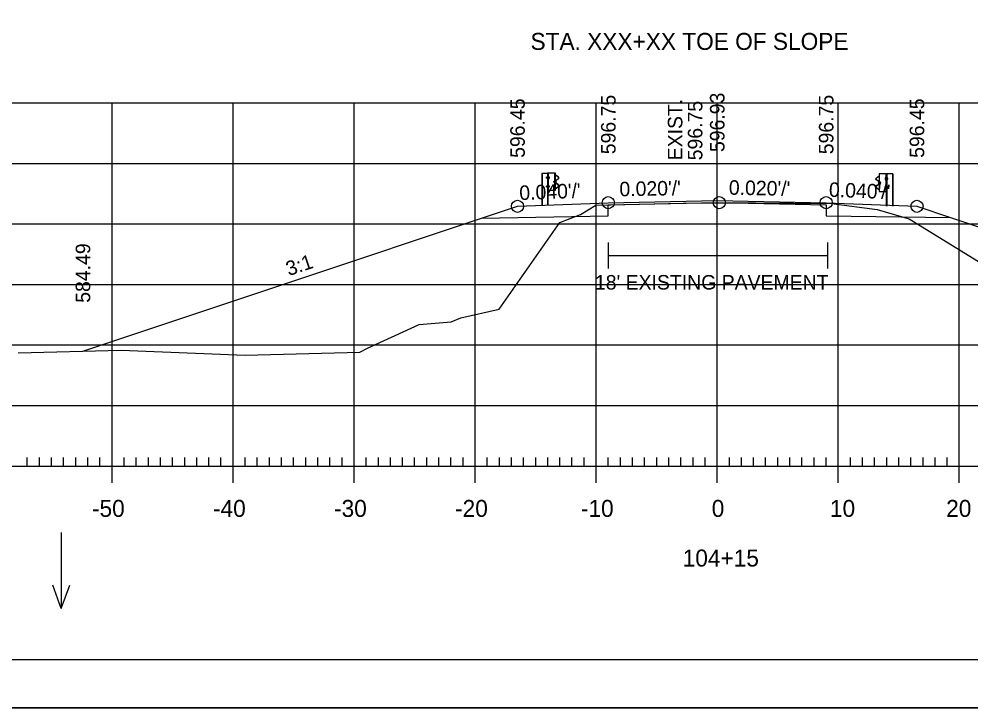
# Model space of a CAD drawing. Extents: x 961436 to 1372525, y 380079 to 2027791.
# Drawn here: x 1370576.1 to 1370654.8, y 380322.4 to 380379.3 of the extents above; entities that cross this region are included whole.
import ezdxf

# ---------------------------------------------------------------- set-up
doc = ezdxf.new("R2010")
doc.units = 0
for name, color, linetype in [('R_Alt Surface', 7, 'Continuous'), ('R_Axis', 7, 'Continuous'), ('R_Axis Annot', 7, 'Continuous'), ('R_Drive', 7, 'Continuous'), ('R_Exist Surface', 7, 'Continuous'), ('R_Fin Surface', 7, 'Continuous'), ('R_Fin Surface Annot', 7, 'Continuous'), ('R_Grid', 7, 'Continuous'), ('R_No Plot', 7, 'Continuous'), ('R_Proposed Road', 7, 'Continuous'), ('R_Water Annot', 7, 'Continuous'), ('R_Xsect Elev', 7, 'Continuous')]:
    doc.layers.add(name, color=color, linetype=linetype)

msp = doc.modelspace()

# ---------------------------------------------------------------- linework, layer by layer
at = {"layer": 'R_Alt Surface'}
msp.add_lwpolyline([(1370614.334, 380362.858), (1370624.812, 380363.068), (1370624.802, 380363.068), (1370624.812, 380363.985), (1370633.812, 380364.165), (1370642.812, 380363.985), (1370642.822, 380363.068), (1370642.812, 380363.068), (1370653.073, 380362.931)], dxfattribs=at)
at = {"layer": 'R_Axis'}
for p, q in [((1370583.812, 380340.997), (1370583.812, 380343.797)), ((1370593.812, 380340.997), (1370593.812, 380343.797)), ((1370603.812, 380340.997), (1370603.812, 380343.797)), ((1370613.812, 380340.997), (1370613.812, 380343.797)), ((1370623.812, 380340.997), (1370623.812, 380343.797)), ((1370633.812, 380340.997), (1370633.812, 380343.797)), ((1370643.812, 380340.997), (1370643.812, 380343.797)), ((1370653.812, 380340.997), (1370653.812, 380343.797)), ((1370576.812, 380342.397), (1370576.812, 380343.097)), ((1370577.812, 380342.397), (1370577.812, 380343.097)), ((1370578.812, 380342.397), (1370578.812, 380343.097)), ((1370579.812, 380342.397), (1370579.812, 380343.097)), ((1370580.812, 380342.397), (1370580.812, 380343.097)), ((1370581.812, 380342.397), (1370581.812, 380343.097)), ((1370582.812, 380342.397), (1370582.812, 380343.097)), ((1370584.812, 380342.397), (1370584.812, 380343.097)), ((1370585.812, 380342.397), (1370585.812, 380343.097)), ((1370586.812, 380342.397), (1370586.812, 380343.097)), ((1370587.812, 380342.397), (1370587.812, 380343.097)), ((1370588.812, 380342.397), (1370588.812, 380343.097)), ((1370589.812, 380342.397), (1370589.812, 380343.097)), ((1370590.812, 380342.397), (1370590.812, 380343.097)), ((1370591.812, 380342.397), (1370591.812, 380343.097)), ((1370592.812, 380342.397), (1370592.812, 380343.097)), ((1370594.812, 380342.397), (1370594.812, 380343.097)), ((1370595.812, 380342.397), (1370595.812, 380343.097)), ((1370596.812, 380342.397), (1370596.812, 380343.097)), ((1370597.812, 380342.397), (1370597.812, 380343.097)), ((1370598.812, 380342.397), (1370598.812, 380343.097)), ((1370599.812, 380342.397), (1370599.812, 380343.097)), ((1370600.812, 380342.397), (1370600.812, 380343.097)), ((1370601.812, 380342.397), (1370601.812, 380343.097)), ((1370602.812, 380342.397), (1370602.812, 380343.097)), ((1370604.812, 380342.397), (1370604.812, 380343.097)), ((1370605.812, 380342.397), (1370605.812, 380343.097)), ((1370606.812, 380342.397), (1370606.812, 380343.097)), ((1370607.812, 380342.397), (1370607.812, 380343.097)), ((1370608.812, 380342.397), (1370608.812, 380343.097)), ((1370609.812, 380342.397), (1370609.812, 380343.097)), ((1370610.812, 380342.397), (1370610.812, 380343.097)), ((1370611.812, 380342.397), (1370611.812, 380343.097)), ((1370612.812, 380342.397), (1370612.812, 380343.097)), ((1370614.812, 380342.397), (1370614.812, 380343.097)), ((1370615.812, 380342.397), (1370615.812, 380343.097)), ((1370616.812, 380342.397), (1370616.812, 380343.097)), ((1370617.812, 380342.397), (1370617.812, 380343.097)), ((1370618.812, 380342.397), (1370618.812, 380343.097)), ((1370619.812, 380342.397), (1370619.812, 380343.097)), ((1370620.812, 380342.397), (1370620.812, 380343.097)), ((1370621.812, 380342.397), (1370621.812, 380343.097)), ((1370622.812, 380342.397), (1370622.812, 380343.097)), ((1370624.812, 380342.397), (1370624.812, 380343.097)), ((1370625.812, 380342.397), (1370625.812, 380343.097)), ((1370626.812, 380342.397), (1370626.812, 380343.097)), ((1370627.812, 380342.397), (1370627.812, 380343.097)), ((1370628.812, 380342.397), (1370628.812, 380343.097)), ((1370629.812, 380342.397), (1370629.812, 380343.097)), ((1370630.812, 380342.397), (1370630.812, 380343.097)), ((1370631.812, 380342.397), (1370631.812, 380343.097)), ((1370632.812, 380342.397), (1370632.812, 380343.097)), ((1370634.812, 380342.397), (1370634.812, 380343.097)), ((1370635.812, 380342.397), (1370635.812, 380343.097)), ((1370636.812, 380342.397), (1370636.812, 380343.097)), ((1370637.812, 380342.397), (1370637.812, 380343.097)), ((1370638.812, 380342.397), (1370638.812, 380343.097)), ((1370639.812, 380342.397), (1370639.812, 380343.097)), ((1370640.812, 380342.397), (1370640.812, 380343.097)), ((1370641.812, 380342.397), (1370641.812, 380343.097)), ((1370642.812, 380342.397), (1370642.812, 380343.097)), ((1370644.812, 380342.397), (1370644.812, 380343.097)), ((1370645.812, 380342.397), (1370645.812, 380343.097)), ((1370646.812, 380342.397), (1370646.812, 380343.097)), ((1370647.812, 380342.397), (1370647.812, 380343.097)), ((1370648.812, 380342.397), (1370648.812, 380343.097)), ((1370649.812, 380342.397), (1370649.812, 380343.097)), ((1370650.812, 380342.397), (1370650.812, 380343.097)), ((1370651.812, 380342.397), (1370651.812, 380343.097)), ((1370652.812, 380342.397), (1370652.812, 380343.097)), ((1370493.812, 380342.397), (1370773.812, 380342.397))]:
    msp.add_line(p, q, dxfattribs=at)
at = {"layer": 'R_Drive'}
for p, q in [((1370624.798, 380360.859), (1370624.798, 380358.723)), ((1370642.926, 380360.859), (1370642.926, 380358.723)), ((1370624.798, 380359.791), (1370642.926, 380359.791))]:
    msp.add_line(p, q, dxfattribs=at)
at = {"layer": 'R_Exist Surface'}
msp.add_lwpolyline([(1370576.066, 380351.749), (1370584.562, 380351.962), (1370594.822, 380351.568), (1370604.291, 380351.812), (1370604.905, 380352.119), (1370609.172, 380354.091), (1370611.827, 380354.298), (1370612.619, 380354.639), (1370615.788, 380355.355), (1370620.797, 380362.515), (1370622.525, 380363.179), (1370623.787, 380363.938), (1370630.996, 380364.114), (1370633.983, 380364.15), (1370637.011, 380364.124), (1370643.25, 380364.093), (1370647.038, 380363.583), (1370649.681, 380362.807), (1370657.05, 380358.284)], dxfattribs=at)
at = {"layer": 'R_Fin Surface'}
msp.add_lwpolyline([(1370581.408, 380351.883), (1370599.495, 380357.91), (1370614.334, 380362.858), (1370617.312, 380363.851), (1370624.812, 380364.151), (1370633.812, 380364.331), (1370642.812, 380364.151), (1370650.312, 380363.851), (1370653.073, 380362.931), (1370664.147, 380359.237), (1370667.766, 380358.029), (1370680.532, 380353.778)], dxfattribs=at)
at = {"layer": 'R_Grid'}
for p, q in [((1370493.812, 380372.397), (1370773.812, 380372.397)), ((1370583.812, 380342.397), (1370583.812, 380372.397)), ((1370593.812, 380342.397), (1370593.812, 380372.397)), ((1370603.812, 380342.397), (1370603.812, 380372.397)), ((1370613.812, 380342.397), (1370613.812, 380372.397)), ((1370623.812, 380342.397), (1370623.812, 380372.397)), ((1370633.812, 380342.397), (1370633.812, 380372.397)), ((1370643.812, 380342.397), (1370643.812, 380372.397)), ((1370653.812, 380342.397), (1370653.812, 380372.397)), ((1370493.812, 380367.397), (1370773.812, 380367.397)), ((1370493.812, 380362.397), (1370773.812, 380362.397)), ((1370493.812, 380357.397), (1370773.812, 380357.397)), ((1370493.812, 380352.397), (1370773.812, 380352.397)), ((1370493.812, 380347.397), (1370773.812, 380347.397)), ((1370493.812, 380342.397), (1370773.812, 380342.397))]:
    msp.add_line(p, q, dxfattribs=at)
at = {"layer": 'R_No Plot'}
for p, q in [((1370791.992, 380326.397), (1370475.812, 380326.397)), ((1370463.411, 380322.418), (1370796.745, 380322.418))]:
    msp.add_line(p, q, dxfattribs=at)
for points in [[(1370463.405, 380535.752), (1370796.745, 380535.752), (1370796.745, 380322.414), (1370463.405, 380322.414)], [(1370709.732, 380531.857), (1370729.352, 380531.857), (1370729.352, 380521.977), (1370745.464, 380521.977), (1370768.664, 380521.977), (1370768.784, 380493.82), (1370791.992, 380493.82), (1370791.992, 380326.397), (1370475.812, 380326.397), (1370475.812, 380531.857)]]:
    msp.add_lwpolyline(points, close=True, dxfattribs=at)
for centre in [(1370617.312, 380363.851), (1370624.812, 380364.151), (1370633.983, 380364.15), (1370642.812, 380364.151), (1370650.312, 380363.851)]:
    msp.add_circle(centre, 0.5, dxfattribs=at)
at = {"layer": 'R_Proposed Road'}
for p, q in [((1370619.312, 380366.601), (1370619.312, 380363.931)), ((1370619.344, 380366.601), (1370619.344, 380363.931)), ((1370619.87, 380366.603), (1370619.796, 380366.6)), ((1370619.834, 380363.931), (1370619.834, 380366.603)), ((1370619.87, 380366.603), (1370619.863, 380366.603)), ((1370620.399, 380365.151), (1370620.399, 380366.595)), ((1370647.225, 380365.071), (1370647.225, 380366.515)), ((1370647.755, 380366.523), (1370647.761, 380366.523)), ((1370647.755, 380366.523), (1370647.828, 380366.52)), ((1370647.791, 380363.851), (1370647.791, 380366.523)), ((1370648.28, 380366.521), (1370648.28, 380363.851)), ((1370648.312, 380366.521), (1370648.312, 380363.851)), ((1370619.737, 380366.166), (1370619.737, 380366.266)), ((1370619.795, 380366.149), (1370619.742, 380366.149)), ((1370619.795, 380366.25), (1370619.743, 380366.25)), ((1370619.795, 380366.182), (1370619.743, 380366.182)), ((1370619.795, 380366.282), (1370619.744, 380366.282)), ((1370619.795, 380366.182), (1370619.75, 380366.182)), ((1370619.795, 380366.149), (1370619.795, 380366.282)), ((1370619.928, 380366.21), (1370619.869, 380366.21)), ((1370619.876, 380366.144), (1370619.929, 380366.144)), ((1370619.877, 380366.276), (1370619.929, 380366.276)), ((1370619.929, 380366.276), (1370619.929, 380366.144)), ((1370620.327, 380365.824), (1370620.327, 380365.925)), ((1370620.386, 380365.808), (1370620.332, 380365.808)), ((1370620.386, 380365.908), (1370620.334, 380365.908)), ((1370620.386, 380365.84), (1370620.334, 380365.84)), ((1370620.386, 380365.941), (1370620.335, 380365.941)), ((1370620.386, 380365.84), (1370620.34, 380365.84)), ((1370620.386, 380365.808), (1370620.386, 380365.941)), ((1370620.552, 380366.374), (1370620.433, 380366.438)), ((1370620.538, 380366.357), (1370620.44, 380366.41)), ((1370620.441, 380365.809), (1370620.443, 380365.948)), ((1370620.466, 380365.808), (1370620.468, 380365.948)), ((1370620.65, 380365.627), (1370620.485, 380365.73)), ((1370620.491, 380366.022), (1370620.673, 380366.133)), ((1370620.663, 380365.648), (1370620.499, 380365.751)), ((1370620.504, 380365.999), (1370620.687, 380366.111)), ((1370620.676, 380366.247), (1370620.538, 380366.357)), ((1370620.69, 380366.264), (1370620.552, 380366.374)), ((1370646.934, 380366.184), (1370647.072, 380366.294)), ((1370647.12, 380365.919), (1370646.938, 380366.031)), ((1370646.948, 380366.167), (1370647.086, 380366.277)), ((1370647.134, 380365.942), (1370646.951, 380366.053)), ((1370646.962, 380365.568), (1370647.125, 380365.671)), ((1370647.072, 380366.294), (1370647.191, 380366.358)), ((1370647.086, 380366.277), (1370647.185, 380366.33)), ((1370647.158, 380365.728), (1370647.156, 380365.868)), ((1370647.184, 380365.729), (1370647.182, 380365.868)), ((1370647.239, 380365.728), (1370647.239, 380365.861)), ((1370647.239, 380365.861), (1370647.29, 380365.861)), ((1370647.239, 380365.828), (1370647.291, 380365.828)), ((1370647.239, 380365.76), (1370647.285, 380365.76)), ((1370647.239, 380365.76), (1370647.291, 380365.76)), ((1370647.239, 380365.728), (1370647.292, 380365.728)), ((1370647.297, 380365.744), (1370647.297, 380365.845)), ((1370647.748, 380366.196), (1370647.695, 380366.196)), ((1370647.695, 380366.196), (1370647.695, 380366.064)), ((1370647.749, 380366.064), (1370647.695, 380366.064)), ((1370647.697, 380366.13), (1370647.756, 380366.13)), ((1370647.829, 380366.069), (1370647.829, 380366.202)), ((1370647.829, 380366.202), (1370647.88, 380366.202)), ((1370647.829, 380366.17), (1370647.881, 380366.17)), ((1370647.829, 380366.102), (1370647.875, 380366.102)), ((1370647.829, 380366.102), (1370647.881, 380366.102)), ((1370647.829, 380366.069), (1370647.882, 380366.069)), ((1370647.888, 380366.086), (1370647.888, 380366.186)), ((1370619.726, 380365.434), (1370619.726, 380365.534)), ((1370619.785, 380365.517), (1370619.732, 380365.517)), ((1370619.785, 380365.449), (1370619.732, 380365.449)), ((1370619.785, 380365.418), (1370619.732, 380365.418)), ((1370619.785, 380365.55), (1370619.733, 380365.55)), ((1370619.785, 380365.449), (1370619.739, 380365.449)), ((1370619.785, 380365.418), (1370619.785, 380365.55)), ((1370619.869, 380365.151), (1370619.832, 380365.151)), ((1370619.928, 380365.483), (1370619.869, 380365.483)), ((1370619.929, 380365.418), (1370619.876, 380365.418)), ((1370619.929, 380365.55), (1370619.877, 380365.55)), ((1370619.929, 380365.418), (1370619.929, 380365.55)), ((1370620.429, 380365.323), (1370620.544, 380365.382)), ((1370620.438, 380365.303), (1370620.559, 380365.365)), ((1370620.544, 380365.382), (1370620.677, 380365.497)), ((1370620.559, 380365.365), (1370620.692, 380365.48)), ((1370647.066, 380365.285), (1370646.932, 380365.4)), ((1370647.081, 380365.302), (1370646.947, 380365.417)), ((1370646.975, 380365.547), (1370647.139, 380365.65)), ((1370647.187, 380365.223), (1370647.066, 380365.285)), ((1370647.195, 380365.243), (1370647.081, 380365.302)), ((1370647.695, 380365.338), (1370647.695, 380365.47)), ((1370647.695, 380365.47), (1370647.748, 380365.47)), ((1370647.695, 380365.338), (1370647.749, 380365.338)), ((1370647.697, 380365.403), (1370647.756, 380365.403)), ((1370647.756, 380365.071), (1370647.792, 380365.071)), ((1370647.84, 380365.338), (1370647.84, 380365.47)), ((1370647.84, 380365.47), (1370647.892, 380365.47)), ((1370647.84, 380365.437), (1370647.893, 380365.437)), ((1370647.84, 380365.369), (1370647.886, 380365.369)), ((1370647.84, 380365.369), (1370647.893, 380365.369)), ((1370647.84, 380365.338), (1370647.893, 380365.338)), ((1370647.898, 380365.354), (1370647.898, 380365.454))]:
    msp.add_line(p, q, dxfattribs=at)
for points in [[(1370619.312, 380366.601), (1370619.796, 380366.6), (1370619.795, 380363.931)], [(1370648.312, 380366.521), (1370647.828, 380366.52), (1370647.83, 380363.851)]]:
    msp.add_lwpolyline(points, dxfattribs=at)
for points in [[(1370620.427, 380366.602), (1370620.426, 380365.151), (1370619.869, 380365.151), (1370619.87, 380366.603)], [(1370647.198, 380366.522), (1370647.199, 380365.071), (1370647.756, 380365.071), (1370647.755, 380366.523)], [(1370619.735, 380366.249), (1370619.735, 380366.183), (1370619.708, 380366.183), (1370619.708, 380366.249)], [(1370619.794, 380366.303), (1370619.794, 380366.125), (1370619.805, 380366.125), (1370619.805, 380366.303)], [(1370619.928, 380366.276), (1370619.928, 380366.144), (1370619.87, 380366.144), (1370619.87, 380366.276)], [(1370620.325, 380365.908), (1370620.325, 380365.841), (1370620.298, 380365.841), (1370620.298, 380365.908)], [(1370620.384, 380365.962), (1370620.384, 380365.784), (1370620.395, 380365.784), (1370620.395, 380365.962)], [(1370647.24, 380365.882), (1370647.24, 380365.704), (1370647.229, 380365.704), (1370647.229, 380365.882)], [(1370647.3, 380365.828), (1370647.3, 380365.761), (1370647.326, 380365.761), (1370647.326, 380365.828)], [(1370647.697, 380366.196), (1370647.697, 380366.064), (1370647.755, 380366.064), (1370647.755, 380366.196)], [(1370647.83, 380366.223), (1370647.83, 380366.045), (1370647.82, 380366.045), (1370647.82, 380366.223)], [(1370647.89, 380366.169), (1370647.89, 380366.103), (1370647.916, 380366.103), (1370647.916, 380366.169)], [(1370619.723, 380365.517), (1370619.723, 380365.451), (1370619.697, 380365.451), (1370619.697, 380365.517)], [(1370619.783, 380365.572), (1370619.783, 380365.393), (1370619.793, 380365.393), (1370619.793, 380365.572)], [(1370619.928, 380365.55), (1370619.928, 380365.418), (1370619.87, 380365.418), (1370619.87, 380365.55)], [(1370647.697, 380365.47), (1370647.697, 380365.338), (1370647.755, 380365.338), (1370647.755, 380365.47)], [(1370647.842, 380365.492), (1370647.842, 380365.313), (1370647.831, 380365.313), (1370647.831, 380365.492)], [(1370647.901, 380365.437), (1370647.901, 380365.371), (1370647.928, 380365.371), (1370647.928, 380365.437)]]:
    msp.add_lwpolyline(points, close=True, dxfattribs=at)
for centre, radius, start, end in [((1370619.761, 380366.265), 0.0234, 134.57445, 222.22441), ((1370619.835, 380366.216), 0.0979, 159.74227, 200.25773), ((1370619.764, 380366.165), 0.0265, 140.93341, 216.62337), ((1370620.351, 380365.924), 0.0234, 134.57445, 222.22441), ((1370620.425, 380365.874), 0.0979, 159.74227, 200.25773), ((1370620.354, 380365.824), 0.0265, 140.93341, 216.62337), ((1370620.515, 380365.798), 0.0747, 171.78044, 246.85364), ((1370620.534, 380365.941), 0.0918, 118.10599, 175.04439), ((1370620.46, 380365.87), 0.0481, 282.95537, 86.06973), ((1370620.515, 380365.798), 0.049, 171.78044, 246.85364), ((1370620.534, 380365.941), 0.066, 118.10599, 175.04439), ((1370620.641, 380366.191), 0.0658, 299.24991, 57.97825), ((1370620.641, 380366.191), 0.0909, 299.24991, 57.97825), ((1370646.983, 380366.111), 0.0909, 122.02175, 240.75009), ((1370646.983, 380366.111), 0.0658, 122.02175, 240.75009), ((1370647.164, 380365.79), 0.0481, 93.93027, 257.04463), ((1370647.091, 380365.861), 0.066, 4.95561, 61.89401), ((1370647.11, 380365.718), 0.049, 293.14636, 8.21956), ((1370647.091, 380365.861), 0.0918, 4.95561, 61.89401), ((1370647.11, 380365.718), 0.0747, 293.14636, 8.21956), ((1370647.274, 380365.844), 0.0234, 317.77559, 45.42555), ((1370647.199, 380365.794), 0.0979, 339.74227, 20.25773), ((1370647.27, 380365.744), 0.0265, 323.37663, 39.06659), ((1370647.864, 380366.185), 0.0234, 317.77559, 45.42555), ((1370647.789, 380366.136), 0.0979, 339.74227, 20.25773), ((1370647.861, 380366.085), 0.0265, 323.37663, 39.06659), ((1370619.749, 380365.533), 0.0234, 134.57445, 222.22441), ((1370619.824, 380365.484), 0.0979, 159.74227, 200.25773), ((1370619.752, 380365.433), 0.0265, 140.93341, 216.62337), ((1370620.603, 380365.549), 0.0907, 325.21842, 59.11995), ((1370620.603, 380365.549), 0.116, 325.21843, 59.11995), ((1370647.022, 380365.469), 0.116, 120.88005, 214.78158), ((1370647.022, 380365.469), 0.0907, 120.88005, 214.78158), ((1370647.875, 380365.453), 0.0234, 317.77559, 45.42555), ((1370647.801, 380365.404), 0.0979, 339.74227, 20.25773), ((1370647.872, 380365.353), 0.0265, 323.37663, 39.06659)]:
    msp.add_arc(centre, radius, start, end, dxfattribs=at)
at = {"layer": 'R_Water Annot'}
for p, q in [((1370579.615, 380336.907), (1370579.615, 380330.622)), ((1370579.615, 380330.622), (1370578.915, 380332.546)), ((1370579.615, 380330.622), (1370580.315, 380332.546))]:
    msp.add_line(p, q, dxfattribs=at)

# ---------------------------------------------------------------- texts
at = {"layer": 'R_Axis Annot'}
for s, p in [('STA. XXX+XX TOE OF SLOPE', (1370618.386, 380376.772)), ('-50', (1370582.153, 380338.197)), ('-40', (1370592.153, 380338.197)), ('-30', (1370602.153, 380338.197)), ('-20', (1370612.153, 380338.197)), ('-10', (1370622.55, 380338.197)), ('0', (1370633.355, 380338.197)), ('10', (1370643.123, 380338.197)), ('20', (1370652.726, 380338.197)), ('104+15', (1370630.957, 380334.097))]:
    msp.add_text(s, height=1.4, dxfattribs=at).set_placement(p)
at = {"layer": 'R_Fin Surface Annot'}
for s, rotation, p in [('596.75', 90, (1370625.412, 380368.151)), ('596.93', 90, (1370634.412, 380368.331)), ('596.75', 90, (1370643.412, 380368.151)), ('596.45', 90, (1370617.912, 380367.851)), ('596.45', 90, (1370650.912, 380367.851)), ("0.040'/'", 2.29061, (1370617.483, 380364.358)), ("0.020'/'", 1.14576, (1370625.741, 380364.67)), ("0.020'/'", 358.85424, (1370634.761, 380364.812)), ("0.040'/'", 357.70939, (1370643.023, 380364.643)), ('584.49', 90, (1370582.008, 380355.883)), ('3:1', 18.43493, (1370598.413, 380358.079))]:
    msp.add_text(s, height=1.2, rotation=rotation, dxfattribs=at).set_placement(p)
msp.add_text("18' EXISTING PAVEMENT", height=1.2, dxfattribs=at).set_placement((1370623.707, 380356.973))
at = {"layer": 'R_Xsect Elev'}
for s, p in [('EXIST. ', (1370630.933, 380367.65)), ('596.75', (1370632.583, 380367.65))]:
    msp.add_text(s, height=1.2, rotation=90, dxfattribs=at).set_placement(p)

doc.saveas('drawing.dxf')
